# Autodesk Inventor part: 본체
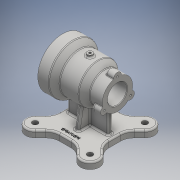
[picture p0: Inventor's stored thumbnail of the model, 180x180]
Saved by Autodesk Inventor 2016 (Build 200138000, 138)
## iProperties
Created: 2017-03
Part Number: 본체
Material: 일반
Document SubType Name: Modeling
Designer: USER
Density: 1 g/cm^3
Appearance: 기본값
Author: USER
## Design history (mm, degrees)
sketch "스케치1"
  geometry: L1 (0, 0)-(-100, 0); L2 (0, 35)-(-23, 35); L3 (-23, 35)-(-23, 26); L4 (-23, 26)-(-70, 26); L5 (-70, 26)-(-70, 17.5); L6 (-70, 17.5)-(-100, 17.5); L7 (-100, 17.5)-(-100, 27.5); L8 (-100, 27.5)-(-77, 27.5); L9 (-77, 27.5)-(-65, 36); L10 (-65, 36)-(-31, 36); L11 (-31, 36)-(-20, 45); L12 (-20, 45)-(0, 45); L13 (0, 45)-(0, 35); 2 further points
  constraints: 26 end point, 7 perpendicular, 2 horizontal, 2 midpoint, 2 parallel, 2 vertical alignment
  dimensions: "d0" = 35 diameter of L6 L1; "d1" = 100 distance between parallel lines of L7 L13; "d2" = 52 diameter of L4 L1; "d3" = 70 diameter of L2 L1; "d4" = 90 diameter of L12 L1; "d5" = 55 diameter of L8 L1; "d6" = 72 diameter of L10 L1; "d7" = 23 distance of L2.start L2.end; "d8" = 47 distance of L3.end L4.end; "d9" = 20 distance of L11.end L12.end; "d11" = 31 horizontal distance of L10.end L12.end; "d12" = 65 distance from line of L9.end L13; "d13" = 23 distance of L7.end L8.end
revolve "회전1" sketch "스케치1" stored, may be unused: angle "d14" = 90 deg
node "작업 평면1"
sketch "스케치2"
  geometry: L1 (5, 45)-(95, 45); L2 (95, 45)-(95, -45); L3 (95, -45)-(5, -45); L4 (5, -45)-(5, 45); L5 (100, 27.5)-(100, -27.5) reference; L6 (50, 45)-(50, -45); L7 (29.042, 45)-(12.095, 61.946); L8 (5, 20.958)-(-11.946, 37.905); L9 (0.075, 49.925)-(99.487, -49.487); L10 (99.073, 49.073)-(0.078, -49.922); C1 r 70 at (50, 0); A1 r 17 centre (0.075, 49.925) between (12.095, 61.946) and (-11.946, 37.905); 4 further points
  constraints: 18 end point, 6 point on line, 4 midpoint, 2 centre point, 2 coincident, 2 horizontal alignment, 2 parallel, 2 point on circle, 2 tangent, 1 horizontal, 1 perpendicular, 1 vertical alignment, 1 other
  dimensions: "d16" = 90 distance of L1.start L1.end; "d17" = 90 distance of L1.end L2.end; "d18" = 50 distance from line of L6 point (0, 0); "d21" = 34 distance between parallel lines of L8 L7; "d26" = 140 diameter of C1; "d27" = 23.96561 distance of L7.start L7.end
extrude "돌출1" join sketch "스케치2" distance "d28" = 12; taper "d29" = 0 deg
extrude "돌출2" join sketch "스케치2" distance "d30" = 12; taper "d31" = 0 deg
node "작업 평면2"
sketch "스케치3"
  geometry: L1 (13, 4)-(87, 4); L2 (87, 4)-(87, -4); L3 (87, -4)-(13, -4); L4 (13, -4)-(13, 4); 3 further points
  constraints: 8 end point, 2 parallel, 1 horizontal, 1 horizontal alignment, 1 midpoint, 1 perpendicular
  dimensions: "d33" = 8 distance of L3.end L1.start; "d34" = 37 distance from line of L4 point (50, 45); "d35" = 37 distance from line of L2 point (50, 45)
extrude "돌출3" join sketch "스케치3" stored distance "d36" = 0; taper "d37" = 0 deg
sketch "스케치4"
  geometry: L1 (-37.905, -70)-(-20.958, -70) reference; L2 (37.905, -70)-(20.958, -70) reference; L3 (0, 0)-(0, -58.122); L4 (-16.238, -20.306)-(-25, -70); L5 (16.238, -20.306)-(25, -70); L6 (-4, -70)-(-4, -44.822) reference; L7 (20.958, -70)-(-20.958, -70) reference; L8 (4, -70)-(4, -44.822) reference; A1 r 26 centre (0, 0) between (-16.238, -20.306) and (16.238, -20.306) reference; 1 further point
  constraints: 6 end point, 2 point on circle, 2 point on line, 1 vertical
  dimensions: "d40" = 25 distance from line of L4.end L3; "d41" = 25 horizontal distance of L3.end L5.end; "d42" = 100 deg angle of L2 L5; "d43" = 100 deg angle of L1 L4
feature "리브1" dims "d44" = 1, "d45" = 8, "d46" = 0, "d47" = 0, "d48" = 1, "d49" = 1
feature "리브2" dims "d50" = 1, "d51" = 8, "d52" = 0, "d53" = 0, "d54" = 1, "d55" = 1
sketch "스케치5"
  geometry: C1 r 5 at (0.075, 49.925); C2 r 5 at (99.925, 49.925); C3 r 5 at (99.925, -49.925); C4 r 5 at (0.075, -49.925); A1 r 17 centre (0.075, 49.925) between (12.095, 61.946) and (-11.946, 37.905) reference; A2 r 17 centre (99.925, 49.925) between (111.946, 37.905) and (87.905, 61.946) reference; A3 r 17 centre (99.925, -49.925) between (87.905, -61.946) and (111.946, -37.905) reference; A4 r 17 centre (0.075, -49.925) between (-11.946, -37.905) and (12.095, -61.946) reference; 1 further point
  constraints: 4 centre point, 3 concentric, 3 equal radius, 1 coincident
  dimensions: "d57" = 10 diameter of C1
extrude "돌출4" cut sketch "스케치5" stored distance "d58" = 0; taper "d59" = 0 deg
node "작업 평면4"
sketch "스케치6"
  geometry: L1 (0, 45)-(0, -45) reference; C1 r 5 at (50, 0); 1 further point
  constraints: 1 centre point, 1 horizontal alignment
  dimensions: "d62" = 10 diameter of C1; "d63" = 50 distance from line of L1 C1.centre
extrude "돌출5" join sketch "스케치6" stored distance "d64" = 15; taper "d65" = 0 deg
sketch "스케치7"
  geometry: C1 r 5 at (0, 0) reference; 2 further points
  constraints: 1 coincident
hole "구멍1" sketch "스케치7" at (0, 0) diameter "d66" = 4.134; stored, may be unused: countersink angle "d70" = 90 deg, drill point angle "d72" = 118 deg; dims "d67" = 10, "d68" = 4, "d69" = 2, "d71" = 14.2
sketch "스케치8"
  geometry: A1 r 27.5 centre (0, 0) between (-27.5, 0) and (-26.609, -6.943) reference; A2 r 7 centre (-27.5, 0) between (-26.609, 6.943) and (-26.609, -6.943); A3 r 27.5 centre (0, 0) between (27.208, 4) and (27.208, -4) reference; 2 further points
  constraints: 6 point on circle, 1 centre point, 1 coincident
  dimensions: "d73" = 7 radius of A2
extrude "돌출6" join sketch "스케치8" distance "d76" = 15; taper "d77" = 0 deg
fillet "모깎기1" dims "d78" = 3
fillet "모깎기2" dims "d79" = 1
sketch "스케치9"
  geometry: A1 r 7 centre (0, 0) between (0.127, 6.999) and (0.127, -6.999) reference; 2 further points
  constraints: 1 coincident
hole "구멍2" sketch "스케치9" at (0, 0) diameter "d83" = 3.242; stored, may be unused: countersink angle "d87" = 90 deg, drill point angle "d89" = 118 deg; dims "d84" = 9, "d85" = 4, "d86" = 2, "d88" = 11
sketch "스케치10" dims "d93" = 80
  geometry: 3 further points
  constraints: 2 horizontal alignment, 1 coincident, 2 other
hole "구멍3" sketch "스케치10" at (40, 0) diameter "d94" = 3.242; stored, may be unused: countersink angle "d98" = 90 deg, drill point angle "d100" = 118 deg; dims "d95" = 9, "d96" = 4, "d97" = 2, "d99" = 11
chamfer "모따기1" distance "d104" = 1; stored, may be unused: second distance "d105" = 2, angle "d106" = 45 deg
fillet "모깎기3" dims "d107" = 3
fillet "모깎기4" dims "d108" = 3
fillet "모깎기5" dims "d109" = 3
fillet "모깎기6" dims "d110" = 3
fillet "모깎기7" dims "d111" = 3
fillet "모깎기8" dims "d112" = 25
fillet "모깎기9" dims "d113" = 3
sketch "스케치11"
  geometry: L1 (95, -10.603)-(95, 10.603) reference; L2 (0, 0)-(121.979, 0); 1 further point
  constraints: 2 end point, 1 horizontal, 1 other
  dimensions: "d114" = 45 distance from line of L1 point (50, -35); "d116" = 35 distance from line of point (50, -35) L2
feature "엠보싱1" sketch "스케치11" dims "d0" = 35, "d1" = 100, "d2" = 52, "d3" = 70, "d4" = 90, "d5" = 55, "d6" = 72, "d7" = 23, "d8" = 47, "d9" = 20, "d11" = 31, "d12" = 65, "d13" = 23, "d16" = 90, "d17" = 90, "d18" = 50, "d21" = 34, "d26" = 140, "d27" = 23.96561, "d117" = 0.5, "d118" = 0
node "솔리드1"
mirror "대칭1"
mirror "대칭2"
pattern_circular "원형 패턴1" dims "d81" = 360 deg
pattern_circular "원형 패턴2" dims angle "d91" = 360 deg
pattern_circular "원형 패턴3" dims angle "d102" = 360 deg
other parameters: "d15" = -82
